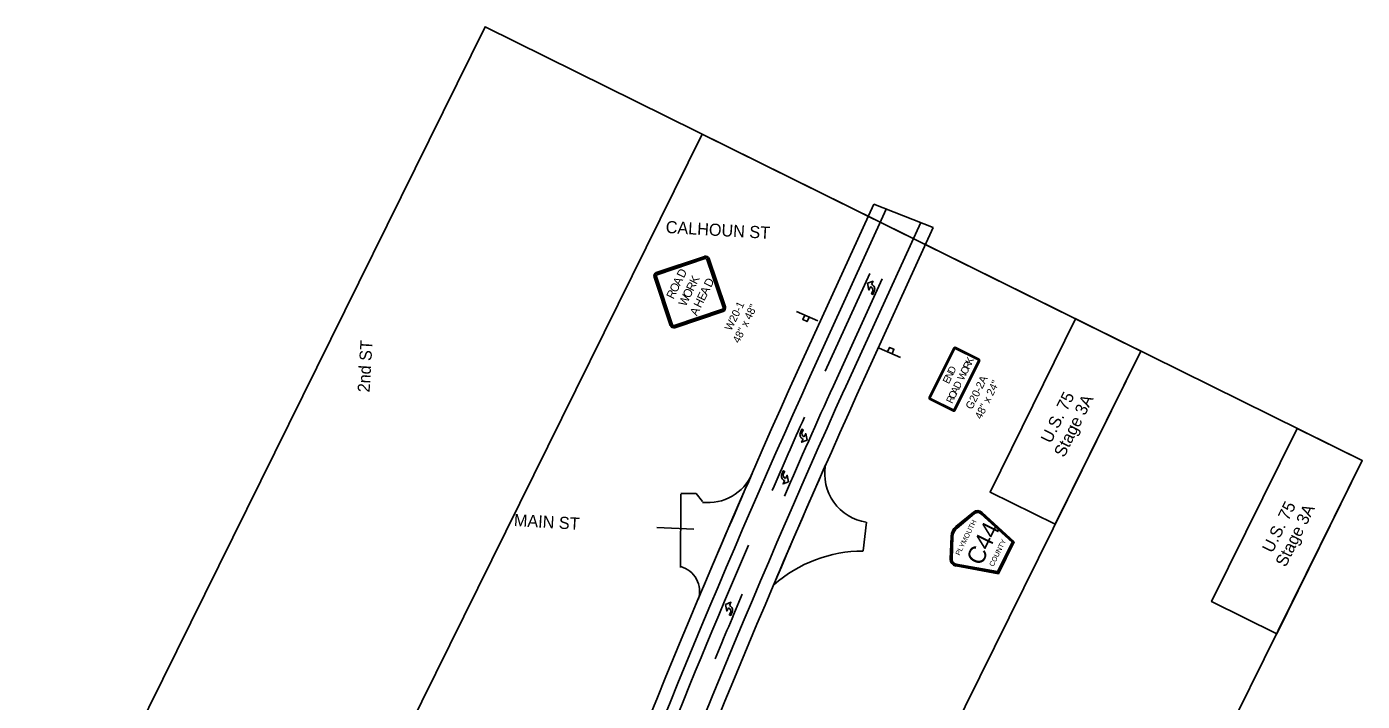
# Model space of a CAD drawing. Extents: x 14104283 to 14120882, y 8635219 to 8671666.
# Drawn here: x 14119504 to 14120882, y 8670970 to 8671666 of the extents above; entities that cross this region are included whole.
import ezdxf

# ---------------------------------------------------------------- set-up
doc = ezdxf.new("R2010")
doc.units = 0
for name, color, linetype in [('Cell', 7, 'Continuous'), ('Default', 7, 'Continuous'), ('dsnNonPlotable', 7, 'Continuous'), ('dsnPaintExistingBrokenLaneLineWhite', 7, 'Continuous'), ('dsnPaintExistingDoubleCenterYellow', 7, 'Continuous'), ('dsnPaintExistingLaneLineWhite', 7, 'Continuous'), ('dsnPaintExistingNoPassingYellow', 7, 'Continuous'), ('dsnPaintExistingSymbolWhite', 7, 'Continuous'), ('dsnTextOverlapEven', 7, 'Continuous'), ('Sign', 7, 'Continuous')]:
    doc.layers.add(name, color=color, linetype=linetype)

msp = doc.modelspace()

# ---------------------------------------------------------------- linework, layer by layer
at = {"layer": 'Cell'}
for p, q in [((14120203.3, 8671428.8), (14120153.5, 8671412)), ((14120203.6, 8671427.9), (14120204.1, 8671426.5)), ((14120205.7, 8671425.7), (14120207.1, 8671426.2)), ((14120224.8, 8671376.7), (14120208, 8671426.5)), ((14120151.2, 8671407.3), (14120168, 8671357.5)), ((14120152.1, 8671407.6), (14120153.6, 8671408.1)), ((14120154.3, 8671409.6), (14120153.8, 8671411.1)), ((14120375.7, 8671399.8), (14120375.9, 8671399.7)), ((14120374.9, 8671397.3), (14120374.6, 8671397.4)), ((14120172.8, 8671355.2), (14120222.5, 8671372)), ((14120221.7, 8671374.4), (14120222.2, 8671372.9)), ((14120224, 8671376.4), (14120222.5, 8671375.9)), ((14120298.1, 8671372), (14120320.1, 8671362.2)), ((14120170.4, 8671358.3), (14120168.9, 8671357.8)), ((14120172.5, 8671356.1), (14120172, 8671357.5)), ((14120405.4, 8671324.5), (14120383.4, 8671334.2)), ((14120460.2, 8671333.9), (14120435.2, 8671283.5)), ((14120460.6, 8671333.7), (14120461.3, 8671333.3)), ((14120462.1, 8671333.6), (14120462.5, 8671334.3)), ((14120486.2, 8671323.1), (14120462.7, 8671334.7)), ((14120462.1, 8671270.2), (14120487, 8671320.6)), ((14120486, 8671322.7), (14120485.6, 8671322)), ((14120485.9, 8671321.2), (14120486.6, 8671320.8)), ((14120436.3, 8671282.9), (14120435.6, 8671283.3)), ((14120436.1, 8671281), (14120459.6, 8671269.3)), ((14120436.3, 8671281.4), (14120436.6, 8671282.1)), ((14120460.2, 8671270.4), (14120459.8, 8671269.7)), ((14120461.7, 8671270.4), (14120461, 8671270.7)), ((14120305, 8671240.3), (14120304.8, 8671240.4)), ((14120305.8, 8671242.8), (14120306.1, 8671242.7)), ((14120228.2, 8671066.1), (14120227.9, 8671066.2)), ((14120229, 8671068.6), (14120229.2, 8671068.5))]:
    msp.add_line(p, q, dxfattribs=at)
for points in [[(14120203.6, 8671427.9), (14120153.8, 8671411.1), (14120154.3, 8671409.6), (14120204.1, 8671426.5), (14120203.6, 8671427.9)], [(14120224, 8671376.4), (14120207.1, 8671426.2), (14120205.7, 8671425.7), (14120222.5, 8671375.9), (14120224, 8671376.4)], [(14120152.1, 8671407.6), (14120168.9, 8671357.8), (14120170.4, 8671358.3), (14120153.6, 8671408.1), (14120152.1, 8671407.6)], [(14120172.5, 8671356.1), (14120222.2, 8671372.9), (14120221.7, 8671374.4), (14120172, 8671357.5), (14120172.5, 8671356.1)], [(14120311.2, 8671366.1), (14120306.7, 8671368.1), (14120304.7, 8671363.6), (14120309.2, 8671361.6)], [(14120392.3, 8671330.4), (14120396.8, 8671328.4), (14120398.7, 8671332.9), (14120394.3, 8671334.9)], [(14120460.6, 8671333.7), (14120435.6, 8671283.3), (14120436.3, 8671282.9), (14120461.3, 8671333.3), (14120460.6, 8671333.7)], [(14120486, 8671322.7), (14120462.5, 8671334.3), (14120462.1, 8671333.6), (14120485.6, 8671322), (14120486, 8671322.7)], [(14120461.7, 8671270.4), (14120486.6, 8671320.8), (14120485.9, 8671321.2), (14120461, 8671270.7), (14120461.7, 8671270.4)], [(14120436.3, 8671281.4), (14120459.8, 8671269.7), (14120460.2, 8671270.4), (14120436.6, 8671282.1), (14120436.3, 8671281.4)]]:
    msp.add_lwpolyline(points, close=True, dxfattribs=at)
for points in [[(14120371.5, 8671401), (14120377.3, 8671403.2), (14120375.7, 8671399.8)], [(14120371.5, 8671401), (14120377.3, 8671403.2), (14120375.7, 8671399.8)], [(14120374.6, 8671397.4), (14120373, 8671394.1), (14120371.5, 8671401)], [(14120374.6, 8671397.4), (14120373, 8671394.1), (14120371.5, 8671401)], [(14120375.7, 8671399.8), (14120375.9, 8671399.7)], [(14120374.9, 8671397.3), (14120374.6, 8671397.4)], [(14120378.5, 8671393), (14120377.1, 8671389.6), (14120375.7, 8671390.2), (14120376.7, 8671392.6)], [(14120378.5, 8671393), (14120377.1, 8671389.6), (14120375.7, 8671390.2), (14120376.7, 8671392.6)], [(14120311.2, 8671366.1), (14120306.7, 8671368.1), (14120304.7, 8671363.6), (14120309.2, 8671361.6), (14120311.2, 8671366.1)], [(14120392.3, 8671330.4), (14120396.8, 8671328.4), (14120398.7, 8671332.9), (14120394.3, 8671334.9), (14120392.3, 8671330.4)], [(14120302.2, 8671247.1), (14120303.6, 8671250.5), (14120305, 8671250), (14120304, 8671247.5)], [(14120302.2, 8671247.1), (14120303.6, 8671250.5), (14120305, 8671250), (14120304, 8671247.5)], [(14120309.1, 8671239.2), (14120303.4, 8671237), (14120305, 8671240.3)], [(14120309.1, 8671239.2), (14120303.4, 8671237), (14120305, 8671240.3)], [(14120305, 8671240.3), (14120304.8, 8671240.4)], [(14120305.8, 8671242.8), (14120306.1, 8671242.7)], [(14120306.1, 8671242.7), (14120307.7, 8671246), (14120309.1, 8671239.2)], [(14120306.1, 8671242.7), (14120307.7, 8671246), (14120309.1, 8671239.2)], [(14120224.8, 8671069.7), (14120230.6, 8671071.9), (14120229, 8671068.6)], [(14120224.8, 8671069.7), (14120230.6, 8671071.9), (14120229, 8671068.6)], [(14120227.9, 8671066.2), (14120226.3, 8671062.9), (14120224.8, 8671069.7)], [(14120227.9, 8671066.2), (14120226.3, 8671062.9), (14120224.8, 8671069.7)], [(14120228.2, 8671066.1), (14120227.9, 8671066.2)], [(14120229, 8671068.6), (14120229.2, 8671068.5)], [(14120231.8, 8671061.8), (14120230.4, 8671058.4), (14120229, 8671058.9), (14120230, 8671061.4)], [(14120231.8, 8671061.8), (14120230.4, 8671058.4), (14120229, 8671058.9), (14120230, 8671061.4)]]:
    msp.add_lwpolyline(points, dxfattribs=at)
for centre, radius, start, end in [((14120204.5, 8671425.3), 3.75, 18.6913, 108.691), ((14120204.5, 8671425.3), 2.81, 18.6913, 108.691), ((14120204.5, 8671425.3), 1.25, 18.6913, 108.691), ((14120154.7, 8671408.5), 3.75, 108.6912, 198.6909), ((14120154.7, 8671408.5), 2.81, 108.6912, 198.6909), ((14120154.7, 8671408.5), 1.25, 108.6912, 198.6909), ((14120221.3, 8671375.5), 1.25, 288.6911, 18.6913), ((14120221.3, 8671375.5), 2.81, 288.6911, 18.6913), ((14120221.3, 8671375.5), 3.75, 288.6911, 18.6913), ((14120171.6, 8671358.7), 1.25, 198.6909, 288.6911), ((14120171.6, 8671358.7), 3.75, 198.6909, 288.6911), ((14120171.6, 8671358.7), 2.81, 198.6909, 288.6911), ((14120461.8, 8671333.1), 1.87, 63.6912, 153.6914), ((14120461.8, 8671333.1), 1.41, 63.6912, 153.6914), ((14120461.8, 8671333.1), 0.625, 63.6912, 153.6914), ((14120485.4, 8671321.4), 0.625, 333.6912, 63.6914), ((14120485.4, 8671321.4), 1.41, 333.6912, 63.6914), ((14120485.4, 8671321.4), 1.87, 333.6912, 63.6914), ((14120436.9, 8671282.6), 1.87, 153.6914, 243.691), ((14120436.9, 8671282.6), 1.41, 153.6914, 243.691), ((14120436.9, 8671282.6), 0.625, 153.6914, 243.691), ((14120460.4, 8671271), 1.87, 243.691, 333.6912), ((14120460.4, 8671271), 1.41, 243.691, 333.6912), ((14120460.4, 8671271), 0.625, 243.691, 333.6912)]:
    msp.add_arc(centre, radius, start, end, dxfattribs=at)
for centre, major_axis in [((14120373.9, 8671394.9), (-2, -4.86)), ((14120373.9, 8671394.9), (-2, -4.86)), ((14120373.5, 8671393.9), (-1.4, -3.4)), ((14120373.5, 8671393.9), (-1.4, -3.4)), ((14120306.8, 8671245.2), (2, 4.86)), ((14120306.8, 8671245.2), (2, 4.86)), ((14120307.2, 8671246.2), (1.4, 3.4)), ((14120307.2, 8671246.2), (1.4, 3.4)), ((14120226.8, 8671062.7), (-1.4, -3.4)), ((14120226.8, 8671062.7), (-1.4, -3.4)), ((14120227.2, 8671063.6), (-2, -4.86)), ((14120227.2, 8671063.6), (-2, -4.86))]:
    msp.add_ellipse(centre, major_axis=major_axis, ratio=0.9474, start_param=1.570796, end_param=3.141593, dxfattribs=at)
at = {"layer": 'Default'}
for p, q in [((14120299, 8671309.7), (14120377.9, 8671482.5)), ((14120377.9, 8671482.5), (14120439.4, 8671458.6)), ((14120439.4, 8671458.6), (14120360.6, 8671285.8)), ((14120178.7, 8671183.5), (14120178.6, 8671107.9)), ((14120178.7, 8671183.5), (14120178.6, 8671107.9)), ((14120194.8, 8671184.3), (14120178.7, 8671184.3)), ((14120194.8, 8671184.3), (14120178.7, 8671184.3)), ((14120201.1, 8671175.8), (14120194.8, 8671184.3)), ((14120201.1, 8671175.8), (14120194.8, 8671184.3)), ((14120370.3, 8671154.6), (14120366.9, 8671124.9)), ((14120370.3, 8671154.6), (14120366.9, 8671124.9))]:
    msp.add_line(p, q, dxfattribs=at)
for centre, radius, start, end in [((14129121.8, 8667322.2), 9682.1, 155.67905, 159.75253), ((14129183.4, 8667298.3), 9682.1, 155.67905, 159.75253), ((14129183.4, 8667298.3), 9682.1, 156.14717, 156.94403), ((14129183.4, 8667298.3), 9682.1, 156.14717, 156.94403), ((14120377.6, 8671204.3), 50.2, 169.2669, 261.6204), ((14120377.6, 8671204.3), 50.2, 169.2669, 261.6204), ((14129121.8, 8667321.8), 9682.1, 156.35706, 157.19061), ((14129121.8, 8667321.8), 9682.1, 156.35706, 157.19061), ((14120206.8, 8671224.6), 49.9, 263.4387, 336.3571), ((14120206.8, 8671224.6), 49.9, 263.4387, 336.3571), ((14120367.2, 8670984.5), 140.3, 90.1123, 131.2245), ((14120367.2, 8670984.5), 140.3, 90.1123, 131.2245), ((14120171.7, 8671083.2), 26.5, 342.4439, 74.5077), ((14120171.7, 8671083.2), 26.5, 342.4439, 74.5077)]:
    msp.add_arc(centre, radius, start, end, dxfattribs=at)
at = {"layer": 'dsnNonPlotable'}
for points in [[(14119282, 8670260.6), (14119976.8, 8671665.7), (14120882.2, 8671218.1), (14120187.4, 8669813)], [(14119506.2, 8670149.8), (14120200.9, 8671554.9), (14120653.6, 8671331.1), (14119958.8, 8669926)]]:
    msp.add_lwpolyline(points, close=True, dxfattribs=at)
at = {"layer": 'dsnPaintExistingBrokenLaneLineWhite'}
for p, q in [((14120312.1, 8671304.6), (14120390.9, 8671477.4)), ((14120347.5, 8671290.9), (14120426.4, 8671463.7))]:
    msp.add_line(p, q, dxfattribs=at)
for centre in [(14129134.9, 8667317.1), (14129170.3, 8667303.4)]:
    msp.add_arc(centre, 9682.1, 155.67905, 159.75253, dxfattribs=at)
at = {"layer": 'dsnPaintExistingDoubleCenterYellow'}
msp.add_line((14120154.2, 8671149.1), (14120192.4, 8671147.3), dxfattribs=at)
at = {"layer": 'dsnPaintExistingLaneLineWhite'}
for centre, start, end in [((14129146.1, 8667312.8), 155.92282, 156.41213), ((14129159.1, 8667307.7), 157.06665, 157.496)]:
    msp.add_arc(centre, 9682.1, start, end, dxfattribs=at)
at = {"layer": 'dsnPaintExistingNoPassingYellow'}
for p, q in [((14120373.9, 8671411.3), (14120327.8, 8671310.2)), ((14120336.3, 8671295.2), (14120386.6, 8671405.5))]:
    msp.add_line(p, q, dxfattribs=at)
for centre, start, end in [((14129159.1, 8667307.7), 155.67905, 156.4156), ((14129146.1, 8667312.8), 156.77428, 159.75253)]:
    msp.add_arc(centre, 9682.1, start, end, dxfattribs=at)
at = {"layer": 'dsnPaintExistingSymbolWhite'}
for p, q in [((14120375.7, 8671399.8), (14120375.9, 8671399.7)), ((14120374.9, 8671397.3), (14120374.6, 8671397.4)), ((14120305, 8671240.3), (14120304.8, 8671240.4)), ((14120305.8, 8671242.8), (14120306.1, 8671242.7)), ((14120285.9, 8671197.3), (14120285.7, 8671197.4)), ((14120286.7, 8671199.8), (14120287, 8671199.7)), ((14120228.2, 8671066.1), (14120227.9, 8671066.2)), ((14120229, 8671068.6), (14120229.2, 8671068.5))]:
    msp.add_line(p, q, dxfattribs=at)
for points in [[(14120371.5, 8671401), (14120377.3, 8671403.2), (14120375.7, 8671399.8)], [(14120371.5, 8671401), (14120377.3, 8671403.2), (14120375.7, 8671399.8)], [(14120374.6, 8671397.4), (14120373, 8671394.1), (14120371.5, 8671401)], [(14120374.6, 8671397.4), (14120373, 8671394.1), (14120371.5, 8671401)], [(14120375.7, 8671399.8), (14120375.9, 8671399.7)], [(14120374.9, 8671397.3), (14120374.6, 8671397.4)], [(14120378.5, 8671393), (14120377.1, 8671389.6), (14120375.7, 8671390.2), (14120376.7, 8671392.6)], [(14120378.5, 8671393), (14120377.1, 8671389.6), (14120375.7, 8671390.2), (14120376.7, 8671392.6)], [(14120302.2, 8671247.1), (14120303.6, 8671250.5), (14120305, 8671250), (14120304, 8671247.5)], [(14120302.2, 8671247.1), (14120303.6, 8671250.5), (14120305, 8671250), (14120304, 8671247.5)], [(14120309.1, 8671239.2), (14120303.4, 8671237), (14120305, 8671240.3)], [(14120309.1, 8671239.2), (14120303.4, 8671237), (14120305, 8671240.3)], [(14120305, 8671240.3), (14120304.8, 8671240.4)], [(14120305.8, 8671242.8), (14120306.1, 8671242.7)], [(14120306.1, 8671242.7), (14120307.7, 8671246), (14120309.1, 8671239.2)], [(14120306.1, 8671242.7), (14120307.7, 8671246), (14120309.1, 8671239.2)], [(14120283.1, 8671204.2), (14120284.5, 8671207.6), (14120285.9, 8671207), (14120284.9, 8671204.6)], [(14120283.1, 8671204.2), (14120284.5, 8671207.6), (14120285.9, 8671207), (14120284.9, 8671204.6)], [(14120290, 8671196.2), (14120284.3, 8671194), (14120285.9, 8671197.3)], [(14120290, 8671196.2), (14120284.3, 8671194), (14120285.9, 8671197.3)], [(14120285.9, 8671197.3), (14120285.7, 8671197.4)], [(14120286.7, 8671199.8), (14120287, 8671199.7)], [(14120287, 8671199.7), (14120288.6, 8671203), (14120290, 8671196.2)], [(14120287, 8671199.7), (14120288.6, 8671203), (14120290, 8671196.2)], [(14120224.8, 8671069.7), (14120230.6, 8671071.9), (14120229, 8671068.6)], [(14120224.8, 8671069.7), (14120230.6, 8671071.9), (14120229, 8671068.6)], [(14120227.9, 8671066.2), (14120226.3, 8671062.9), (14120224.8, 8671069.7)], [(14120227.9, 8671066.2), (14120226.3, 8671062.9), (14120224.8, 8671069.7)], [(14120228.2, 8671066.1), (14120227.9, 8671066.2)], [(14120229, 8671068.6), (14120229.2, 8671068.5)], [(14120231.8, 8671061.8), (14120230.4, 8671058.4), (14120229, 8671058.9), (14120230, 8671061.4)], [(14120231.8, 8671061.8), (14120230.4, 8671058.4), (14120229, 8671058.9), (14120230, 8671061.4)]]:
    msp.add_lwpolyline(points, dxfattribs=at)
for centre, major_axis in [((14120373.9, 8671394.9), (-2, -4.86)), ((14120373.9, 8671394.9), (-2, -4.86)), ((14120373.5, 8671393.9), (-1.4, -3.4)), ((14120373.5, 8671393.9), (-1.4, -3.4)), ((14120306.8, 8671245.2), (2, 4.86)), ((14120306.8, 8671245.2), (2, 4.86)), ((14120307.2, 8671246.2), (1.4, 3.4)), ((14120307.2, 8671246.2), (1.4, 3.4)), ((14120287.7, 8671202.3), (2, 4.86)), ((14120287.7, 8671202.3), (2, 4.86)), ((14120288.1, 8671203.2), (1.4, 3.4)), ((14120288.1, 8671203.2), (1.4, 3.4)), ((14120226.8, 8671062.7), (-1.4, -3.4)), ((14120226.8, 8671062.7), (-1.4, -3.4)), ((14120227.2, 8671063.6), (-2, -4.86)), ((14120227.2, 8671063.6), (-2, -4.86))]:
    msp.add_ellipse(centre, major_axis=major_axis, ratio=0.9474, start_param=1.570796, end_param=3.141593, dxfattribs=at)
at = {"layer": 'dsnTextOverlapEven'}
for points in [[(14120653.6, 8671331.1), (14120565.3, 8671152.5), (14120498, 8671185.7), (14120586.3, 8671364.3)], [(14120498, 8671185.7), (14120586.3, 8671364.3), (14120653.6, 8671331.1), (14120565.3, 8671152.5)], [(14120882.2, 8671218.1), (14120793.8, 8671039.4), (14120726.6, 8671072.7), (14120814.9, 8671251.3)], [(14120726.6, 8671072.7), (14120814.9, 8671251.3), (14120882.2, 8671218.1), (14120793.8, 8671039.4)]]:
    msp.add_lwpolyline(points, close=True, dxfattribs=at)
at = {"layer": 'Sign'}
for p, q in [((14120462.7, 8671150), (14120480.8, 8671164.9)), ((14120481.4, 8671164.1), (14120463.3, 8671149.3)), ((14120463.3, 8671149.3), (14120481.4, 8671164.1)), ((14120464, 8671148.5), (14120482, 8671163.4)), ((14120482, 8671163.4), (14120464, 8671148.5)), ((14120488.6, 8671163.2), (14120520.7, 8671133.9)), ((14120520.7, 8671133.9), (14120488.6, 8671163.2)), ((14120521.9, 8671134.2), (14120489.3, 8671163.9)), ((14120489.3, 8671163.9), (14120521.9, 8671134.2)), ((14120489.9, 8671164.6), (14120523, 8671134.4)), ((14120456.9, 8671116.5), (14120457.7, 8671139.9)), ((14120458.7, 8671139.8), (14120457.8, 8671116.4)), ((14120457.8, 8671116.4), (14120458.7, 8671139.8)), ((14120458.8, 8671116.4), (14120459.7, 8671139.8)), ((14120459.7, 8671139.8), (14120458.8, 8671116.4)), ((14120520.7, 8671133.9), (14120505.7, 8671103.6)), ((14120505.7, 8671103.6), (14120520.7, 8671133.9)), ((14120506.2, 8671102.5), (14120521.9, 8671134.2)), ((14120521.9, 8671134.2), (14120506.2, 8671102.5)), ((14120523, 8671134.4), (14120506.7, 8671101.4)), ((14120523, 8671134.4), (14120521.9, 8671134.2)), ((14120462.8, 8671110.3), (14120506.2, 8671102.5)), ((14120506.2, 8671102.5), (14120462.8, 8671110.3)), ((14120505.7, 8671103.6), (14120462.9, 8671111.3)), ((14120462.9, 8671111.3), (14120505.7, 8671103.6)), ((14120506.7, 8671101.4), (14120462.6, 8671109.4)), ((14120505.7, 8671103.6), (14120506.2, 8671102.5))]:
    msp.add_line(p, q, dxfattribs=at)
for centre, radius, start, end in [((14120485.2, 8671159.5), 6.97, 47.5883, 129.4611), ((14120485.2, 8671159.5), 5.99, 47.5883, 129.4611), ((14120485.2, 8671159.5), 5.99, 47.5883, 129.4611), ((14120485.2, 8671159.5), 5.02, 47.5883, 129.4611), ((14120485.2, 8671159.5), 5.02, 47.5883, 129.4611), ((14120471.5, 8671139.4), 13.8, 129.4611, 177.9213), ((14120471.5, 8671139.4), 12.8, 129.4611, 177.9213), ((14120471.5, 8671139.4), 12.8, 129.4611, 177.9213), ((14120471.5, 8671139.4), 11.8, 129.4611, 177.9213), ((14120471.5, 8671139.4), 11.8, 129.4611, 177.9213), ((14120463.8, 8671116.2), 6.97, 177.9213, 259.7941), ((14120463.8, 8671116.2), 5.99, 177.9213, 259.7941), ((14120463.8, 8671116.2), 5.99, 177.9213, 259.7941), ((14120463.8, 8671116.2), 5.02, 177.9213, 259.7941), ((14120463.8, 8671116.2), 5.02, 177.9213, 259.7941)]:
    msp.add_arc(centre, radius, start, end, dxfattribs=at)

# ---------------------------------------------------------------- texts
at = {"layer": 'Cell'}
for s, height, p in [('D', 8.75, (14120181.9, 8671405.8)), ('O', 8.75, (14120174.5, 8671390.8)), ('A', 8.75, (14120178, 8671397.8)), ('R', 8.75, (14120191.6, 8671392.2)), ('K', 8.75, (14120195.1, 8671399.3)), ('D', 8.75, (14120210, 8671396.2)), ('R', 8.75, (14120171.2, 8671384.1)), ('W', 8.75, (14120183.8, 8671376.5)), ('O', 8.75, (14120188, 8671384.9)), ('E', 8.75, (14120203, 8671382.2)), ('A', 8.75, (14120205.9, 8671388)), ('A', 8.75, (14120195.4, 8671366.7)), ('H', 8.75, (14120199.4, 8671374.9)), ('W20-1', 8, (14120230.8, 8671351.4)), ('48" x 48"', 8, (14120239, 8671338.6)), ('R', 7.5, (14120476.3, 8671311.6)), ('K', 7.5, (14120478.8, 8671316.6)), ('E', 7.5, (14120455.4, 8671296.7)), ('N', 7.5, (14120457.7, 8671301.5)), ('D', 7.5, (14120460.4, 8671306.9)), ('W', 7.5, (14120470.6, 8671300.1)), ('O', 7.5, (14120473.7, 8671306.3)), ('G20-2A', 8, (14120479.4, 8671270.2)), ('O', 7.5, (14120461.2, 8671281.1)), ('A', 7.5, (14120463.7, 8671286.1)), ('D', 7.5, (14120466.3, 8671291.4)), ('48" x 24"', 8, (14120488.9, 8671260.1)), ('R', 7.5, (14120458.9, 8671276.3))]:
    msp.add_text(s, height=height, rotation=63.6912, dxfattribs=at).set_placement(p)
at = {"layer": 'dsnTextOverlapEven'}
for s, rotation, p in [('CALHOUN ST', 356.6912, (14120163, 8671453)), ('2nd ST', 86.6912, (14119857.6, 8671288.2)), ('U.S. 75', 63.6912, (14120560.8, 8671235.1)), ('Stage 3A', 63.6912, (14120574.5, 8671220.6)), ('U.S. 75', 63.6912, (14120789.3, 8671122)), ('Stage 3A', 63.6912, (14120803.1, 8671107.5)), ('MAIN ST', 356.6912, (14120006.3, 8671150.6))]:
    msp.add_text(s, height=12.5, rotation=rotation, dxfattribs=at).set_placement(p)
at = {"layer": 'Sign'}
for s, height, p in [('PLYMOUTH', 5.18, (14120466.6, 8671119.8)), ('C44', 18.14, (14120488.9, 8671108.7)), ('COUNTY', 5.18, (14120501.4, 8671108.3))]:
    msp.add_text(s, height=height, rotation=63.6912, dxfattribs=at).set_placement(p)

doc.saveas('drawing.dxf')
